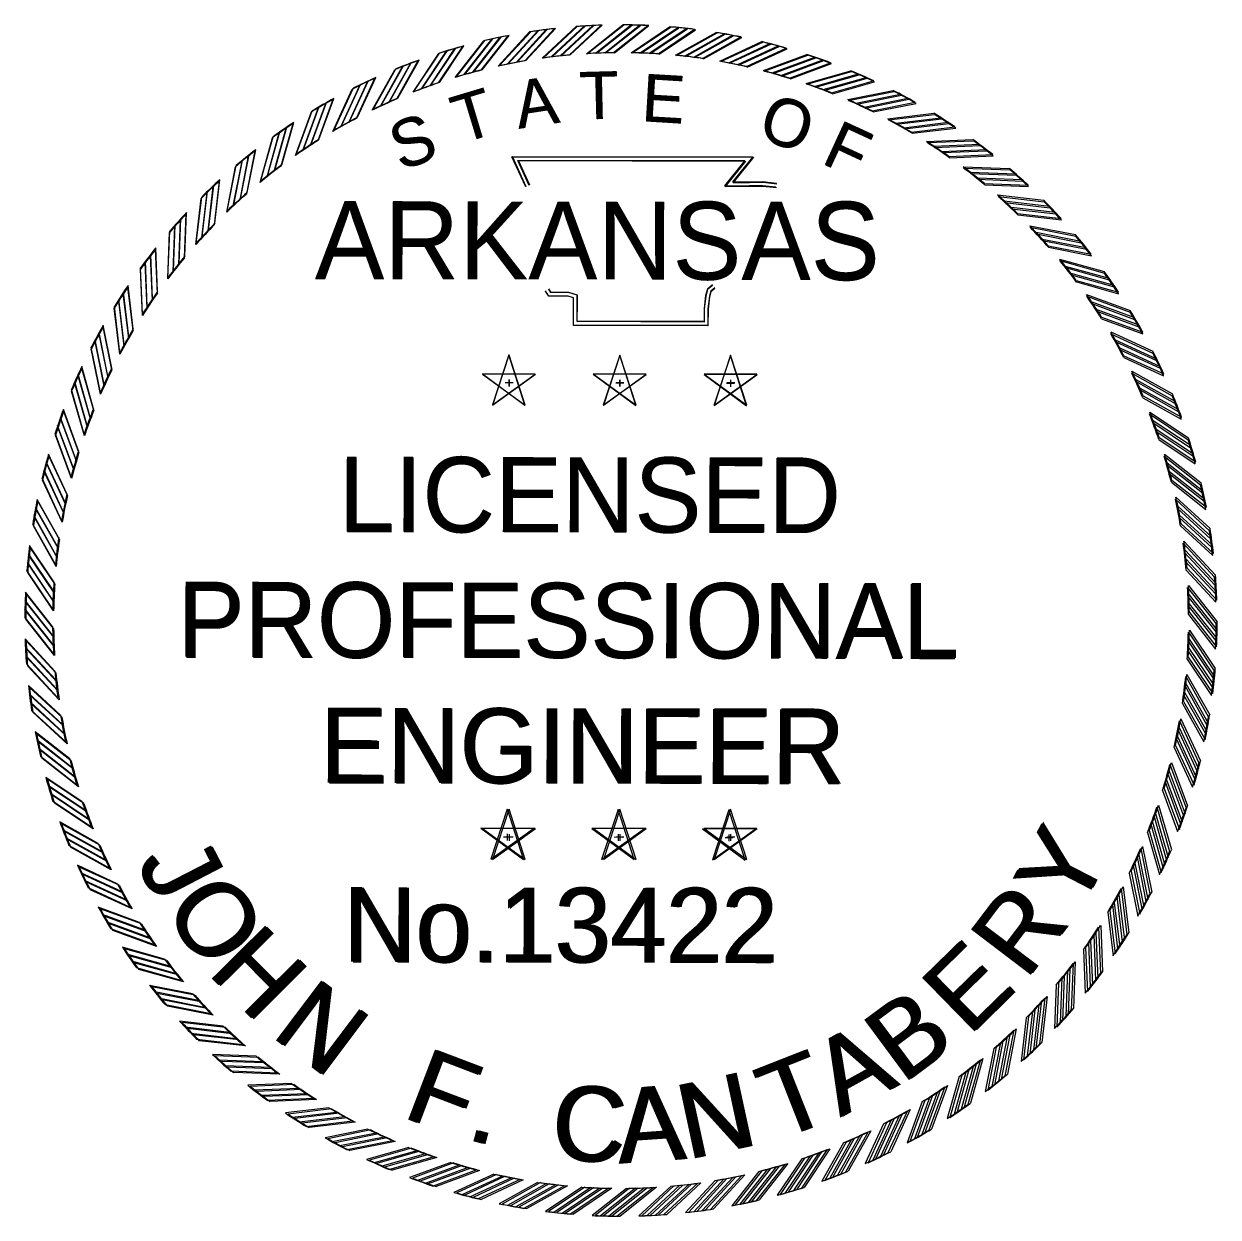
# Model space of a CAD drawing. Extents: x 759422 to 1467393, y 1662254 to 1691786.
# Drawn here: x 1467267.4 to 1467388.9, y 1691456.6 to 1691578 of the extents above; entities that cross this region are included whole.
import ezdxf

# ---------------------------------------------------------------- set-up
doc = ezdxf.new("R2010")
doc.units = 0
doc.layers.add('Default', color=7, linetype='Continuous')

# ---------------------------------------------------------------- blocks, each defined once
blk = doc.blocks.new('STAR')
at = {"layer": 'Default'}
for p, q in [((-0.0001, 0.0615), (-0.0366, -0.0504)), ((0.0362, -0.0503), (0, 0.0617)), ((0.0587, 0.0188), (-0.059, 0.0189)), ((-0.0589, 0.0188), (0.0363, -0.0505)), ((-0.0365, -0.0503), (0.0589, 0.0188)), ((-0.0085, 0), (0.009, 0)), ((0, 0.0063), (0, -0.0085))]:
    blk.add_line(p, q, dxfattribs=at)
blk = doc.blocks.new('RP')
at = {"layer": 'Default'}
for p, q in [((-0.0781, 1.2656), (0.003, 1.33)), ((-0.058, 1.2667), (0.0216, 1.3299)), ((-0.0375, 1.2674), (0.0405, 1.3294)), ((-0.0176, 1.2679), (0.059, 1.3287))]:
    blk.add_line(p, q, dxfattribs=at)
for radius, start, end in [(1.33, 87.4562, 89.8699), (1.268, 90.7933, 93.5307)]:
    blk.add_arc((0, 0), radius, start, end, dxfattribs=at)

msp = doc.modelspace()

# ---------------------------------------------------------------- linework, layer by layer
at = {"layer": 'Default'}
for points in [[(1467318.47, 1691561.42), (1467317.05, 1691564.48), (1467341.57, 1691564.5), (1467339.52, 1691561.93), (1467341.19, 1691561.95), (1467342.58, 1691561.96), (1467343.97, 1691561.81)], [(1467318.52, 1691561.43), (1467317.11, 1691564.51), (1467341.63, 1691564.44), (1467339.57, 1691561.87), (1467341.24, 1691561.89), (1467342.63, 1691561.9), (1467344.02, 1691561.74)], [(1467318.82, 1691561.58), (1467317.66, 1691564.1), (1467340.77, 1691564.11), (1467338.71, 1691561.53), (1467341.19, 1691561.56), (1467342.56, 1691561.58), (1467343.93, 1691561.43)], [(1467318.87, 1691561.59), (1467317.72, 1691564.12), (1467340.82, 1691564.05), (1467338.76, 1691561.47), (1467341.24, 1691561.5), (1467342.61, 1691561.51), (1467343.98, 1691561.36)], [(1467337.71, 1691551.14), (1467337.29, 1691550.8), (1467337.15, 1691550.29), (1467337.01, 1691549.02), (1467337.01, 1691547.33), (1467323.32, 1691547.33), (1467323.32, 1691549.61), (1467323.32, 1691550.12), (1467322.77, 1691550.29), (1467320.82, 1691550.29), (1467320.48, 1691550.82)], [(1467337.72, 1691551.09), (1467337.3, 1691550.75), (1467337.16, 1691550.24), (1467337.02, 1691548.97), (1467337.01, 1691547.28), (1467323.32, 1691547.33), (1467323.33, 1691549.61), (1467323.33, 1691550.12), (1467322.78, 1691550.29), (1467320.83, 1691550.3), (1467320.49, 1691550.83)], [(1467337.46, 1691551.44), (1467336.95, 1691551.02), (1467336.77, 1691550.36), (1467336.62, 1691549.04), (1467336.62, 1691547.71), (1467323.71, 1691547.71), (1467323.71, 1691549.61), (1467323.71, 1691550.41), (1467322.83, 1691550.68), (1467321.03, 1691550.68), (1467320.8, 1691551.03)], [(1467337.48, 1691551.39), (1467336.96, 1691550.98), (1467336.78, 1691550.32), (1467336.63, 1691549), (1467336.63, 1691547.67), (1467323.71, 1691547.71), (1467323.72, 1691549.61), (1467323.72, 1691550.41), (1467322.84, 1691550.68), (1467321.04, 1691550.69), (1467320.81, 1691551.04)]]:
    msp.add_lwpolyline(points, dxfattribs=at)

# ---------------------------------------------------------------- block references
for name, p, xscale, yscale, rotation in [('RP', (1467328.21, 1691517.29), 45.5882767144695, 45.58827671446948, 9.000000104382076), ('RP', (1467328.11, 1691517.28), 45.58827671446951, 45.58827671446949, 8.804199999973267), ('RP', (1467328.21, 1691517.29), 45.58827671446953, 45.5882767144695, 4.500000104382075), ('RP', (1467328.11, 1691517.28), 45.58827671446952, 45.58827671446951, 4.304199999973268), ('RP', (1467328.21, 1691517.29), 45.58827671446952, 45.588276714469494, 1.0438208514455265e-07), ('RP', (1467328.11, 1691517.28), 45.588276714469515, 45.5882767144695, -0.19580000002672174), ('RP', (1467328.21, 1691517.29), 45.58827671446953, 45.58827671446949, -4.499999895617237), ('RP', (1467328.11, 1691517.28), 45.58827671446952, 45.58827671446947, -4.695800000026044), ('RP', (1467328.21, 1691517.29), 45.58827671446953, 45.58827671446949, -8.999999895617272), ('RP', (1467328.11, 1691517.28), 45.588276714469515, 45.5882767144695, -9.195800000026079), ('RP', (1467328.21, 1691517.29), 45.58827671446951, 45.58827671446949, 13.500000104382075), ('RP', (1467328.11, 1691517.28), 45.588276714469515, 45.5882767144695, 13.304199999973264), ('RP', (1467328.21, 1691517.29), 45.58827671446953, 45.5882767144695, -13.499999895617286), ('RP', (1467328.11, 1691517.28), 45.58827671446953, 45.5882767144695, -13.695800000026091), ('RP', (1467328.21, 1691517.29), 45.58827671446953, 45.588276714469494, 18.000000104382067), ('RP', (1467328.11, 1691517.28), 45.588276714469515, 45.58827671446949, 17.80419999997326), ('RP', (1467328.21, 1691517.29), 45.58827671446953, 45.5882767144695, -17.999999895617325), ('RP', (1467328.11, 1691517.28), 45.58827671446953, 45.588276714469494, -18.195800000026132), ('RP', (1467328.21, 1691517.29), 45.588276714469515, 45.5882767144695, 22.500000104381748), ('RP', (1467328.11, 1691517.28), 45.58827671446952, 45.588276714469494, 22.304199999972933), ('RP', (1467328.21, 1691517.29), 45.58827671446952, 45.588276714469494, -22.499999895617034), ('RP', (1467328.11, 1691517.28), 45.588276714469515, 45.5882767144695, -22.695800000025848), ('RP', (1467328.21, 1691517.29), 45.588276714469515, 45.58827671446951, 27.00000010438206), ('RP', (1467328.11, 1691517.28), 45.58827671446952, 45.5882767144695, 26.80419999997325), ('RP', (1467328.21, 1691517.29), 45.58827671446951, 45.588276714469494, -26.999999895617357), ('RP', (1467328.11, 1691517.28), 45.588276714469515, 45.58827671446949, -27.19580000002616), ('RP', (1467328.21, 1691517.29), 45.588276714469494, 45.58827671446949, 31.500000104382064), ('RP', (1467328.11, 1691517.28), 45.588276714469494, 45.58827671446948, 31.304199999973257), ('RP', (1467328.21, 1691517.29), 45.58827671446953, 45.588276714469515, -31.499999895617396), ('RP', (1467328.11, 1691517.28), 45.58827671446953, 45.588276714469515, -31.695800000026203), ('RP', (1467328.21, 1691517.29), 45.58827671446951, 45.588276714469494, 36.000000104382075), ('RP', (1467328.11, 1691517.28), 45.588276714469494, 45.58827671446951, 35.80419999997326), ('RP', (1467328.21, 1691517.29), 45.58827671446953, 45.588276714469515, -35.99999989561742), ('RP', (1467328.11, 1691517.28), 45.58827671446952, 45.58827671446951, -36.195800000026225), ('RP', (1467328.11, 1691517.28), 45.5882767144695, 45.588276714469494, 40.30419999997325), ('RP', (1467328.21, 1691517.29), 45.588276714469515, 45.588276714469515, -40.49999989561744), ('RP', (1467328.11, 1691517.28), 45.588276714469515, 45.58827671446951, -40.69580000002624), ('RP', (1467328.21, 1691517.29), 45.5882767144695, 45.5882767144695, 40.50000010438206), ('RP', (1467328.21, 1691517.29), 45.5882767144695, 45.588276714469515, 45.00000010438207), ('RP', (1467328.11, 1691517.28), 45.5882767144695, 45.5882767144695, 44.80419999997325), ('RP', (1467328.21, 1691517.29), 45.588276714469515, 45.58827671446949, -44.99999989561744), ('RP', (1467328.11, 1691517.28), 45.588276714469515, 45.58827671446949, -45.195800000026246), ('RP', (1467328.21, 1691517.29), 45.5882767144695, 45.5882767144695, -49.499999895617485), ('RP', (1467328.11, 1691517.28), 45.588276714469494, 45.58827671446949, -49.69580000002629), ('RP', (1467328.21, 1691517.29), 45.588276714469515, 45.58827671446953, 49.500000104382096), ('RP', (1467328.11, 1691517.28), 45.588276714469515, 45.58827671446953, 49.30419999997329), ('RP', (1467328.21, 1691517.29), 45.58827671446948, 45.588276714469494, -53.999999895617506), ('RP', (1467328.11, 1691517.28), 45.58827671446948, 45.588276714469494, -54.1958000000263), ('RP', (1467328.21, 1691517.29), 45.588276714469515, 45.58827671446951, 54.00000010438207), ('RP', (1467328.11, 1691517.28), 45.588276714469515, 45.5882767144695, 53.804199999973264), ('RP', (1467328.21, 1691517.29), 45.588276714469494, 45.5882767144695, -58.49999989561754), ('RP', (1467328.11, 1691517.28), 45.58827671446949, 45.58827671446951, 58.30419999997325), ('RP', (1467328.21, 1691517.29), 45.588276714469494, 45.58827671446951, 58.50000010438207), ('RP', (1467328.11, 1691517.28), 45.5882767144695, 45.58827671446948, -58.695800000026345), ('RP', (1467328.11, 1691517.28), 45.5882767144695, 45.58827671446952, 62.804199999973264), ('RP', (1467328.21, 1691517.29), 45.58827671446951, 45.588276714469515, 63.000000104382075), ('RP', (1467328.21, 1691517.29), 45.588276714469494, 45.58827671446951, -62.99999989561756), ('RP', (1467328.11, 1691517.28), 45.588276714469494, 45.58827671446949, -63.19580000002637), ('STAR', (1467316.74, 1691541.52), 45.588276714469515, 45.5882767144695, -0.19580000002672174), ('STAR', (1467316.76, 1691541.5), 45.58827671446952, 45.588276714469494, 1.0438208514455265e-07), ('STAR', (1467328.02, 1691541.49), 45.588276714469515, 45.5882767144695, -0.19580000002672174), ('STAR', (1467328.04, 1691541.5), 45.58827671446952, 45.588276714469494, 1.0438208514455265e-07), ('STAR', (1467339.3, 1691541.45), 45.588276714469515, 45.5882767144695, -0.19580000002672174), ('STAR', (1467339.32, 1691541.5), 45.58827671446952, 45.588276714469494, 1.0438208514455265e-07), ('RP', (1467328.11, 1691517.28), 45.588276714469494, 45.58827671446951, -67.69580000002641), ('RP', (1467328.21, 1691517.29), 45.5882767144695, 45.588276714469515, -67.49999989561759), ('RP', (1467328.11, 1691517.28), 45.588276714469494, 45.58827671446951, 67.30419999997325), ('RP', (1467328.21, 1691517.29), 45.588276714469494, 45.58827671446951, 67.50000010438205), ('RP', (1467328.11, 1691517.28), 45.5882767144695, 45.58827671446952, 71.80419999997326), ('RP', (1467328.21, 1691517.29), 45.5882767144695, 45.58827671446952, 72.00000010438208), ('RP', (1467328.11, 1691517.28), 45.588276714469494, 45.58827671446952, -72.19580000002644), ('RP', (1467328.21, 1691517.29), 45.5882767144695, 45.5882767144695, -71.99999989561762), ('RP', (1467328.21, 1691517.29), 45.58827671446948, 45.588276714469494, -76.49999989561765), ('RP', (1467328.11, 1691517.28), 45.588276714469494, 45.58827671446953, 76.30419999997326), ('RP', (1467328.21, 1691517.29), 45.58827671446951, 45.588276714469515, 76.50000010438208), ('RP', (1467328.11, 1691517.28), 45.58827671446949, 45.588276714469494, -76.69580000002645), ('RP', (1467328.11, 1691517.28), 45.588276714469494, 45.58827671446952, -81.19580000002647), ('RP', (1467328.21, 1691517.29), 45.58827671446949, 45.588276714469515, -80.99999989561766), ('RP', (1467328.11, 1691517.28), 45.58827671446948, 45.588276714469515, 80.80419999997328), ('RP', (1467328.21, 1691517.29), 45.58827671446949, 45.588276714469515, 81.0000001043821), ('RP', (1467328.11, 1691517.28), 45.58827671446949, 45.588276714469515, -85.69580000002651), ('RP', (1467328.21, 1691517.29), 45.588276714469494, 45.58827671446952, -85.49999989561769), ('RP', (1467328.11, 1691517.28), 45.58827671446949, 45.58827671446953, 85.30419999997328), ('RP', (1467328.21, 1691517.29), 45.5882767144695, 45.58827671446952, 85.50000010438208), ('RP', (1467328.11, 1691517.28), 45.588276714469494, 45.58827671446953, -90.19580000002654), ('RP', (1467328.21, 1691517.29), 45.588276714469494, 45.588276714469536, -89.99999989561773), ('RP', (1467328.11, 1691517.28), 45.588276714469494, 45.58827671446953, 89.80419999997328), ('RP', (1467328.21, 1691517.29), 45.58827671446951, 45.588276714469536, 90.0000001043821), ('RP', (1467328.11, 1691517.28), 45.588276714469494, 45.588276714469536, 94.30419999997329), ('RP', (1467328.21, 1691517.29), 45.5882767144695, 45.58827671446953, 94.5000001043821), ('RP', (1467328.11, 1691517.28), 45.588276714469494, 45.58827671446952, -94.69580000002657), ('RP', (1467328.21, 1691517.29), 45.58827671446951, 45.58827671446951, -94.49999989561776), ('RP', (1467328.21, 1691517.29), 45.588276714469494, 45.58827671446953, -98.99999989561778), ('RP', (1467328.11, 1691517.28), 45.588276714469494, 45.5882767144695, 98.8041999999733), ('RP', (1467328.21, 1691517.29), 45.58827671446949, 45.58827671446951, 99.0000001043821), ('RP', (1467328.11, 1691517.28), 45.588276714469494, 45.58827671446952, -99.19580000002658), ('RP', (1467328.11, 1691517.28), 45.5882767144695, 45.588276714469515, -103.69580000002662), ('RP', (1467328.21, 1691517.29), 45.588276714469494, 45.58827671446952, -103.49999989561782), ('RP', (1467328.11, 1691517.28), 45.588276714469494, 45.58827671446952, 103.30419999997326), ('RP', (1467328.21, 1691517.29), 45.588276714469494, 45.58827671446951, 103.50000010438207), ('RP', (1467328.11, 1691517.28), 45.5882767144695, 45.58827671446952, 107.80419999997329), ('RP', (1467328.21, 1691517.29), 45.58827671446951, 45.588276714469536, 108.0000001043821), ('RP', (1467328.11, 1691517.28), 45.58827671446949, 45.58827671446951, -108.19580000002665), ('RP', (1467328.21, 1691517.29), 45.58827671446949, 45.588276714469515, -107.99999989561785), ('RP', (1467328.21, 1691517.29), 45.588276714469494, 45.58827671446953, -112.49999989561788), ('RP', (1467328.11, 1691517.28), 45.588276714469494, 45.58827671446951, 112.30419999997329), ('RP', (1467328.21, 1691517.29), 45.58827671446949, 45.58827671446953, 112.5000001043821), ('STAR', (1467316.58, 1691495.28), 45.588276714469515, 45.5882767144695, -0.19580000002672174), ('STAR', (1467316.76, 1691495.26), 45.58827671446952, 45.588276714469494, 1.0438208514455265e-07), ('STAR', (1467327.86, 1691495.25), 45.588276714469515, 45.5882767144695, -0.19580000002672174), ('STAR', (1467328.04, 1691495.26), 45.58827671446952, 45.588276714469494, 1.0438208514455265e-07), ('STAR', (1467339.14, 1691495.21), 45.588276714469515, 45.5882767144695, -0.19580000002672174), ('STAR', (1467339.32, 1691495.26), 45.58827671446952, 45.588276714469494, 1.0438208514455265e-07), ('RP', (1467328.11, 1691517.28), 45.58827671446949, 45.58827671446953, -112.69580000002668), ('RP', (1467328.11, 1691517.28), 45.58827671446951, 45.588276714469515, 116.80419999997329), ('RP', (1467328.21, 1691517.29), 45.58827671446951, 45.588276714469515, 117.0000001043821), ('RP', (1467328.11, 1691517.28), 45.58827671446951, 45.58827671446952, -117.19580000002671), ('RP', (1467328.21, 1691517.29), 45.588276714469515, 45.58827671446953, -116.9999998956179), ('RP', (1467328.11, 1691517.28), 45.5882767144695, 45.58827671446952, -121.69580000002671), ('RP', (1467328.21, 1691517.29), 45.5882767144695, 45.58827671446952, -121.4999998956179), ('RP', (1467328.11, 1691517.28), 45.58827671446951, 45.588276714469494, 121.30419999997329), ('RP', (1467328.21, 1691517.29), 45.58827671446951, 45.58827671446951, 121.5000001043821), ('RP', (1467328.21, 1691517.29), 45.588276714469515, 45.588276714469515, -125.99999989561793), ('RP', (1467328.11, 1691517.28), 45.588276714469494, 45.5882767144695, 125.80419999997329), ('RP', (1467328.21, 1691517.29), 45.588276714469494, 45.5882767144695, 126.00000010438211), ('RP', (1467328.11, 1691517.28), 45.588276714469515, 45.58827671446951, -126.19580000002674), ('RP', (1467328.11, 1691517.28), 45.588276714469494, 45.5882767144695, 130.3041999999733), ('RP', (1467328.21, 1691517.29), 45.5882767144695, 45.5882767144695, 130.50000010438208), ('RP', (1467328.11, 1691517.28), 45.5882767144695, 45.5882767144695, -130.6958000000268), ('RP', (1467328.21, 1691517.29), 45.58827671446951, 45.588276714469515, -130.49999989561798), ('RP', (1467328.21, 1691517.29), 45.5882767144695, 45.588276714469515, -134.99999989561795), ('RP', (1467328.11, 1691517.28), 45.5882767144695, 45.5882767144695, 134.80419999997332), ('RP', (1467328.21, 1691517.29), 45.58827671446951, 45.58827671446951, 135.0000001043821), ('RP', (1467328.11, 1691517.28), 45.5882767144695, 45.5882767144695, -135.19580000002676), ('RP', (1467328.11, 1691517.28), 45.5882767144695, 45.5882767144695, 139.30419999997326), ('RP', (1467328.11, 1691517.28), 45.588276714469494, 45.58827671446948, -139.69580000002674), ('RP', (1467328.21, 1691517.29), 45.5882767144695, 45.58827671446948, -139.49999989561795), ('RP', (1467328.21, 1691517.29), 45.58827671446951, 45.588276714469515, 139.50000010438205), ('RP', (1467328.11, 1691517.28), 45.58827671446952, 45.5882767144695, 143.8041999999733), ('RP', (1467328.21, 1691517.29), 45.58827671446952, 45.58827671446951, 144.00000010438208), ('RP', (1467328.11, 1691517.28), 45.58827671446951, 45.588276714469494, -144.19580000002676), ('RP', (1467328.21, 1691517.29), 45.58827671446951, 45.588276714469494, -143.99999989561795), ('RP', (1467328.11, 1691517.28), 45.5882767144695, 45.588276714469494, 148.3041999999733), ('RP', (1467328.21, 1691517.29), 45.5882767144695, 45.5882767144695, 148.50000010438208), ('RP', (1467328.11, 1691517.28), 45.58827671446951, 45.58827671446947, -148.69580000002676), ('RP', (1467328.21, 1691517.29), 45.5882767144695, 45.58827671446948, -148.49999989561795), ('RP', (1467328.11, 1691517.28), 45.58827671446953, 45.5882767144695, 152.8041999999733), ('RP', (1467328.21, 1691517.29), 45.588276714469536, 45.58827671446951, 153.00000010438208), ('RP', (1467328.11, 1691517.28), 45.58827671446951, 45.58827671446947, -153.1958000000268), ('RP', (1467328.21, 1691517.29), 45.58827671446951, 45.58827671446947, -152.99999989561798), ('RP', (1467328.11, 1691517.28), 45.588276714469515, 45.58827671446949, 157.3041999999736), ('RP', (1467328.21, 1691517.29), 45.588276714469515, 45.58827671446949, 157.50000010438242), ('RP', (1467328.11, 1691517.28), 45.588276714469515, 45.5882767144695, -157.6958000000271), ('RP', (1467328.21, 1691517.29), 45.588276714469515, 45.5882767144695, -157.4999998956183), ('RP', (1467328.11, 1691517.28), 45.58827671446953, 45.588276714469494, 161.8041999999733), ('RP', (1467328.21, 1691517.29), 45.588276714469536, 45.588276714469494, 162.00000010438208), ('RP', (1467328.11, 1691517.28), 45.588276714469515, 45.5882767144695, -162.19580000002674), ('RP', (1467328.21, 1691517.29), 45.58827671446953, 45.5882767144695, -161.99999989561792), ('RP', (1467328.11, 1691517.28), 45.588276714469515, 45.5882767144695, -166.69580000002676), ('RP', (1467328.21, 1691517.29), 45.58827671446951, 45.58827671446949, -166.49999989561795), ('RP', (1467328.11, 1691517.28), 45.58827671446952, 45.588276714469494, 166.3041999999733), ('RP', (1467328.21, 1691517.29), 45.58827671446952, 45.588276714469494, 166.50000010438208), ('RP', (1467328.11, 1691517.28), 45.58827671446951, 45.58827671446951, 170.8041999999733), ('RP', (1467328.21, 1691517.29), 45.588276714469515, 45.5882767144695, 171.00000010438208), ('RP', (1467328.11, 1691517.28), 45.5882767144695, 45.588276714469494, -171.19580000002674), ('RP', (1467328.21, 1691517.29), 45.5882767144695, 45.58827671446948, -170.99999989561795), ('RP', (1467328.11, 1691517.28), 45.588276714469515, 45.5882767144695, 175.3041999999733), ('RP', (1467328.21, 1691517.29), 45.588276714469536, 45.58827671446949, 175.50000010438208), ('RP', (1467328.11, 1691517.28), 45.58827671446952, 45.5882767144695, 179.8041999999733), ('RP', (1467328.21, 1691517.29), 45.588276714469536, 45.58827671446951, -179.99999989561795), ('RP', (1467328.11, 1691517.28), 45.58827671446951, 45.588276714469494, -175.69580000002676), ('RP', (1467328.21, 1691517.29), 45.588276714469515, 45.58827671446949, -175.49999989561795)]:
    msp.add_blockref(name, p, dxfattribs=dict(at, xscale=xscale, yscale=yscale, rotation=rotation))

# ---------------------------------------------------------------- texts
for s, height, rotation, p in [('A', 4.84, 8.483, (1467317.79, 1691567.34)), ('T', 4.84, 1.4789, (1467323.97, 1691568.28)), ('T', 4.84, 1.2831, (1467324.04, 1691568.28)), ('E', 4.84, 356.672, (1467330.16, 1691568.13)), ('E', 4.84, 356.4762, (1467330.23, 1691568.11)), ('T', 4.84, 16.9015, (1467311.85, 1691565.79)), ('T', 4.84, 16.7057, (1467311.91, 1691565.82)), ('A', 4.84, 8.6788, (1467317.72, 1691567.32)), ('O', 4.84, 341.2218, (1467341.9, 1691566.48)), ('O', 4.84, 341.026, (1467341.97, 1691566.41)), ('S', 4.84, 19.7726, (1467305.7, 1691563.02)), ('S', 4.84, 19.5768, (1467305.75, 1691563.08)), ('F', 4.84, 335.3628, (1467348.42, 1691563.93)), ('F', 4.84, 335.167, (1467348.48, 1691563.84)), ('ARKANSAS', 7.894, 0, (1467297.01, 1691552.02)), ('ARKANSAS', 7.894, 359.8042, (1467297.02, 1691552.11)), ('LICENSED', 7.642, 359.8042, (1467299.39, 1691526.34)), ('LICENSED', 7.642, 0, (1467299.46, 1691526.25)), ('PROFESSIONAL', 7.6424, 359.8042, (1467282.97, 1691513.61)), ('PROFESSIONAL', 7.6424, 0, (1467283.08, 1691513.47)), ('ENGINEER', 7.642, 359.8042, (1467297.48, 1691500.78)), ('ENGINEER', 7.642, 0, (1467297.64, 1691500.69)), ('Y', 7.64, 62.5392, (1467374.69, 1691487.28)), ('Y', 7.64, 62.735, (1467374.9, 1691487.46)), ('J', 7.64, 297.2813, (1467278.71, 1691492.71)), ('J', 7.64, 297.4771, (1467278.89, 1691492.56)), ('O', 7.64, 304.1899, (1467281.41, 1691488.03)), ('O', 7.64, 304.3857, (1467281.62, 1691487.88)), ('No.13422', 7.612, 359.8042, (1467299.83, 1691482.55)), ('No.13422', 7.612, 0, (1467300.05, 1691482.47)), ('R', 7.64, 52.9395, (1467369.59, 1691480.71)), ('R', 7.64, 52.7437, (1467369.36, 1691480.55)), ('H', 7.64, 314.7447, (1467285.92, 1691481.44)), ('H', 7.64, 314.9405, (1467286.15, 1691481.32)), ('E', 7.64, 44.306, (1467363.54, 1691474.87)), ('E', 7.64, 44.5018, (1467363.78, 1691475)), ('N', 7.64, 322.9417, (1467292.37, 1691475.05)), ('N', 7.64, 323.1375, (1467292.62, 1691474.95)), ('B', 7.64, 36.505, (1467356.79, 1691470)), ('B', 7.64, 36.7008, (1467357.06, 1691470.12)), ('A', 7.64, 28.8562, (1467350.44, 1691466.67)), ('A', 7.64, 29.052, (1467350.72, 1691466.76)), ('F', 7.64, 339.0288, (1467305.71, 1691466.78)), ('F', 7.64, 339.2246, (1467305.99, 1691466.72)), ('T', 7.64, 21.4329, (1467344.09, 1691464.28)), ('T', 7.64, 21.6287, (1467344.37, 1691464.35)), ('N', 7.64, 12.0703, (1467334.87, 1691462.37)), ('N', 7.64, 12.2661, (1467335.16, 1691462.41)), ('C', 7.64, 356.1028, (1467320.88, 1691462.49)), ('C', 7.64, 356.2986, (1467321.17, 1691462.48)), ('A', 7.64, 3.9092, (1467327.89, 1691461.98)), ('A', 7.64, 4.105, (1467328.18, 1691462)), ('.', 7.64, 344.7037, (1467312.23, 1691464.52)), ('.', 7.64, 344.8995, (1467312.52, 1691464.48))]:
    msp.add_text(s, height=height, rotation=rotation, dxfattribs=at).set_placement(p)

doc.saveas('drawing.dxf')
